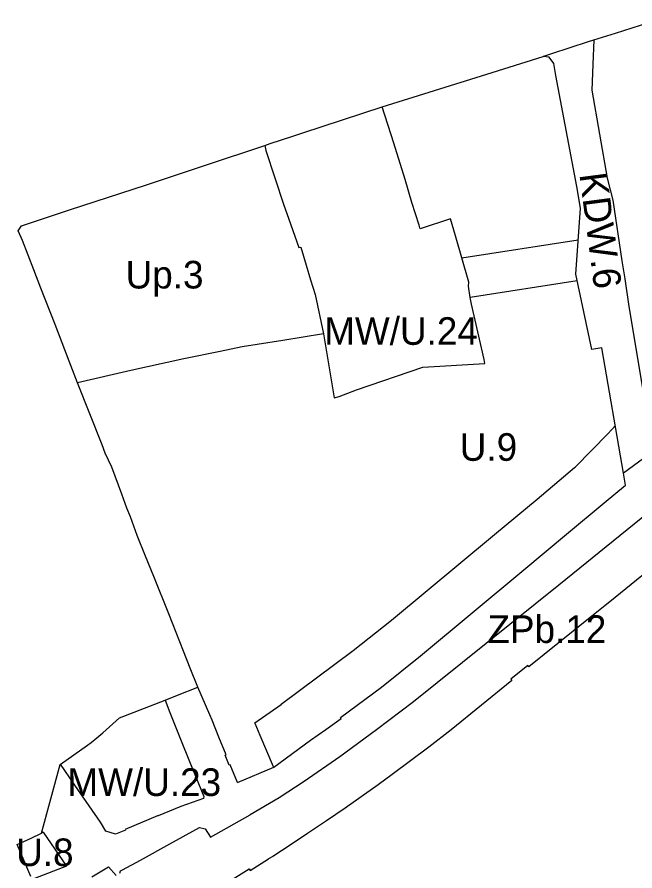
# Model space of a CAD drawing. Extents: x 7421697 to 7426767, y 5545731 to 5547485.
# Drawn here: x 7424539.2 to 7424808, y 5546194.5 to 5546565.8 of the extents above; entities that cross this region are included whole.
import ezdxf

# ---------------------------------------------------------------- set-up
doc = ezdxf.new("R2010")
doc.units = 0
for name, color, linetype in [('LIN_Linia Zabudowy Nieprzekraczalna', 7, 'Continuous'), ('LIN_linie_rozgraniczajace', 7, 'Continuous'), ('TXT_oznaczenia_przeznaczen', 7, 'Continuous')]:
    doc.layers.add(name, color=color, linetype=linetype)

msp = doc.modelspace()

# ---------------------------------------------------------------- linework, layer by layer
at = {"layer": 'LIN_Linia Zabudowy Nieprzekraczalna'}
msp.add_line((7424782.86, 5546451.13), (7424736.39, 5546443.88), dxfattribs=at)
for points in [[(7424732.76, 5546461.08), (7424783.33, 5546468.98)], [(7424650.85, 5546239.79), (7424644.94, 5546253.37), (7424642.79, 5546258.63), (7424642.68, 5546258.92), (7424654.15, 5546266.93), (7424654.09, 5546267.03), (7424685.49, 5546290.33), (7424702.08, 5546303.6), (7424746.94, 5546340.79), (7424765.44, 5546356.26), (7424781.79, 5546369.91), (7424782.16, 5546370.23), (7424796.15, 5546384.55), (7424799.45, 5546388.11)]]:
    msp.add_lwpolyline(points, dxfattribs=at)
at = {"layer": 'LIN_linie_rozgraniczajace'}
for p, q in [((7424550.56, 5546211.37), (7424549.86, 5546211.03)), ((7424640.62, 5546194.7), (7424648.65, 5546199.77)), ((7424632.03, 5546190.43), (7424640.26, 5546195.44)), ((7424640.26, 5546195.44), (7424640.62, 5546194.7))]:
    msp.add_line(p, q, dxfattribs=at)
for points in [[(7424545.19, 5546192.12), (7424539.23, 5546206), (7424545.3, 5546208.8), (7424549.86, 5546211.03), (7424557.93, 5546240.76), (7424569.93, 5546249.26), (7424571.44, 5546250.36), (7424573.99, 5546252.46), (7424576.53, 5546254.57), (7424583.81, 5546261.05), (7424603.65, 5546268.86), (7424608.98, 5546270.95), (7424617.91, 5546274.47), (7424614.55, 5546282.71), (7424611.67, 5546290.06), (7424605.21, 5546306.29), (7424598.75, 5546322.51), (7424595.13, 5546331.45), (7424591.51, 5546340.39), (7424590.02, 5546344.44), (7424588.52, 5546348.5), (7424587.04, 5546352.21), (7424584.82, 5546358.39), (7424580.47, 5546370.11), (7424577.6, 5546376.12), (7424576.21, 5546379.83), (7424565.58, 5546406.74), (7424565.55, 5546406.83), (7424561.93, 5546416.26), (7424555.78, 5546432.1), (7424549.64, 5546447.94), (7424546.51, 5546455.96), (7424544.07, 5546462.28), (7424541.62, 5546468.6), (7424539.74, 5546472.92), (7424541.11, 5546474.97), (7424551.61, 5546478.51), (7424562.11, 5546482.06), (7424595.52, 5546492.88), (7424621.23, 5546501.41), (7424646.94, 5546509.94), (7424649.3, 5546510.78), (7424659.14, 5546514), (7424663.53, 5546515.44), (7424698.1, 5546526.79), (7424743.55, 5546540.92), (7424768.05, 5546548.66), (7424768.38, 5546548.76), (7424771.89, 5546549.92), (7424787.74, 5546555.12), (7424790.18, 5546555.9), (7424799.61, 5546558.88), (7424821.33, 5546565.81)], [(7424790.18, 5546555.9), (7424789.73, 5546545.24), (7424789.21, 5546533.97), (7424795.89, 5546495.73), (7424798.41, 5546486.14), (7424802.25, 5546459.86)], [(7424782.26, 5546453.96), (7424784.3, 5546482.66), (7424782.7, 5546492.1), (7424773.61, 5546540.35), (7424772.72, 5546545.65), (7424770.77, 5546548.32), (7424768.05, 5546548.66)], [(7424672.49, 5546428.01), (7424677.2, 5546400.22), (7424679.39, 5546400.88), (7424683.14, 5546402.29), (7424686.89, 5546403.71), (7424715.71, 5546413.6), (7424742.76, 5546415.13), (7424742.57, 5546416.04), (7424742.39, 5546416.95), (7424736.89, 5546440.94), (7424736.39, 5546443.88), (7424735.56, 5546448.79), (7424735.79, 5546450.59), (7424729.98, 5546470.74), (7424727.78, 5546478.09), (7424714.6, 5546473.8), (7424714.45, 5546474.23), (7424714.21, 5546475.35), (7424711.02, 5546485.22), (7424708.05, 5546495.12), (7424703.07, 5546510.95), (7424698.1, 5546526.79)], [(7424646.94, 5546509.94), (7424647.51, 5546507.81), (7424655.31, 5546484.06), (7424656.52, 5546480.39), (7424661.73, 5546465.58), (7424662.68, 5546465.78), (7424665.05, 5546457.91), (7424666.94, 5546451.53), (7424668.84, 5546445.14), (7424672.49, 5546428.01), (7424654.82, 5546425.22), (7424637.14, 5546422.42), (7424627.56, 5546420.43), (7424611.77, 5546417.27), (7424588.75, 5546412.07), (7424565.55, 5546406.83)], [(7424822.97, 5546382.56), (7424845.44, 5546400.66), (7424872.04, 5546422.11), (7424950.72, 5546485.16), (7424961.42, 5546471.98), (7424959.87, 5546470.73), (7424956.58, 5546463.82), (7424896.17, 5546416.91), (7424774.86, 5546318.83), (7424711.72, 5546268.13), (7424695.62, 5546255.91), (7424679.64, 5546244.15), (7424664.13, 5546233.37), (7424653.19, 5546226.32), (7424640.7, 5546218.87)], [(7424802.25, 5546459.86), (7424803.55, 5546452.04), (7424805.29, 5546440.02), (7424814.36, 5546386.26), (7424822.97, 5546382.56)], [(7424802.97, 5546367.53), (7424793.65, 5546422.05), (7424789.22, 5546421.29), (7424782.26, 5546453.96)], [(7424822.97, 5546382.56), (7424817.62, 5546378.25), (7424815.92, 5546376.99), (7424813.83, 5546375.46), (7424811.74, 5546373.94), (7424802.97, 5546367.53)], [(7424635.07, 5546232.93), (7424650.88, 5546239.72), (7424666.93, 5546251.35), (7424666.9, 5546251.44), (7424673.57, 5546256.09), (7424680.25, 5546260.76), (7424679.95, 5546261.3), (7424697.79, 5546274.47), (7424714.71, 5546288.09), (7424759.74, 5546325.42), (7424778.27, 5546340.91), (7424794.62, 5546354.57), (7424803.9, 5546362.33), (7424802.97, 5546367.53)], [(7424821.96, 5546331.72), (7424799.35, 5546313.46), (7424781.15, 5546298.77), (7424761.92, 5546283.26), (7424761.43, 5546283.92), (7424754.01, 5546277.97), (7424754.51, 5546277.32), (7424741.32, 5546266.63), (7424728, 5546255.92), (7424718.4, 5546248.32), (7424702.45, 5546236.5), (7424696.35, 5546232.05), (7424681.98, 5546221.89), (7424673.79, 5546216.32), (7424665.61, 5546210.76), (7424658.04, 5546205.81), (7424650.47, 5546200.86), (7424648.65, 5546199.77)], [(7424635.07, 5546232.93), (7424631.9, 5546240.7), (7424631.45, 5546240.52), (7424629.7, 5546244.85), (7424630.15, 5546245.03), (7424626.99, 5546252.77), (7424624.1, 5546260.03), (7424623.14, 5546262.44), (7424617.91, 5546274.47)], [(7424603.65, 5546268.86), (7424605.69, 5546263.37), (7424608.02, 5546257.58), (7424610.36, 5546251.8), (7424614.27, 5546242.11), (7424620.41, 5546226.89), (7424620.29, 5546226), (7424610.42, 5546222.62), (7424600.66, 5546218.54), (7424600.39, 5546218.52), (7424586.29, 5546212.58), (7424586.39, 5546212.33), (7424582.06, 5546210.52), (7424577.85, 5546211.79), (7424575.46, 5546215.75), (7424564.37, 5546231.89), (7424564.1, 5546232.21), (7424558.18, 5546240.94)], [(7424583.87, 5546193.55), (7424584.26, 5546194.6), (7424585.13, 5546195.02), (7424592.97, 5546199.25), (7424605.75, 5546206.37), (7424618.53, 5546213.49), (7424621.11, 5546212.82), (7424623.31, 5546209.21), (7424640.7, 5546218.87)], [(7424550.56, 5546211.37), (7424560.75, 5546196.68), (7424546.86, 5546191.31)], [(7424571.69, 5546192.01), (7424579.06, 5546196.33), (7424582.31, 5546192.49)]]:
    msp.add_lwpolyline(points, dxfattribs=at)

# ---------------------------------------------------------------- texts
at = {"layer": 'TXT_oznaczenia_przeznaczen'}
msp.add_text('KDW.6', height=12, rotation=277.442, dxfattribs=at).set_placement((7424783.82, 5546497.49))
for s, p in [('Up.3', (7424586.44, 5546447.8)), ('MW/U.24', (7424672.83, 5546423.3)), ('U.9', (7424731.82, 5546372.87)), ('ZPb.12', (7424743.83, 5546293.68)), ('MW/U.23', (7424561.14, 5546227.13)), ('U.8', (7424538.83, 5546196.64))]:
    msp.add_text(s, height=12, dxfattribs=at).set_placement(p)

doc.saveas('drawing.dxf')
